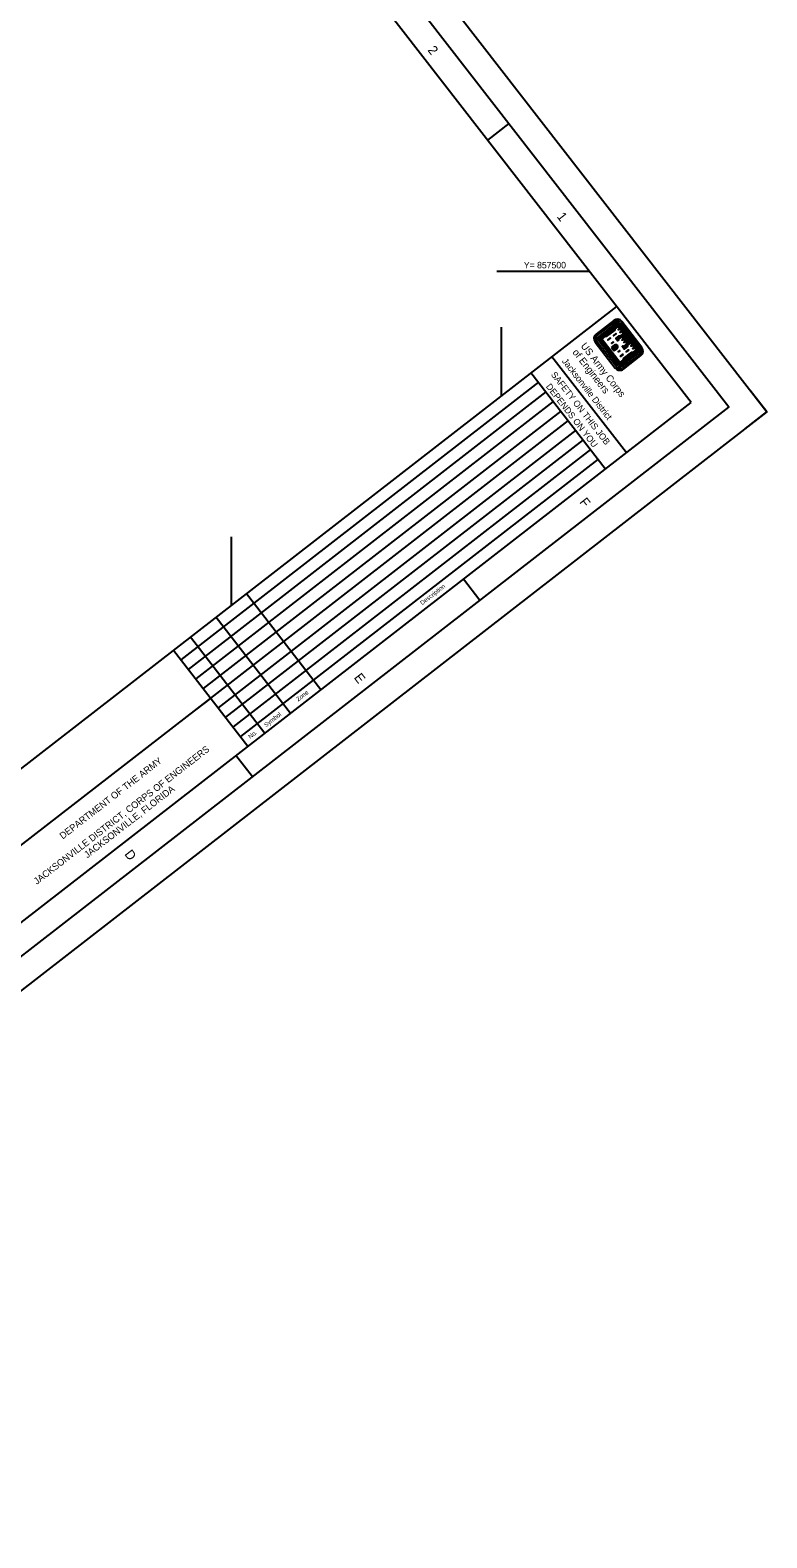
# Model space of a CAD drawing. Extents: x 577607 to 582991, y 855154 to 860715.
# Drawn here: x 581627 to 582991, y 855154 to 857946 of the extents above; entities that cross this region are included whole.
import ezdxf

# ---------------------------------------------------------------- set-up
doc = ezdxf.new("R2010")
doc.units = 0
for name, color, linetype in [('G-ANNO-NPLT', 7, 'Continuous'), ('G-ANNO-TEXT-LOGO', 7, 'Continuous'), ('G-ANNO-TEXT-TTLB', 7, 'Continuous'), ('G-ANNO-TTLB', 7, 'Continuous'), ('V-TOPO-COOR-STAT', 7, 'Continuous')]:
    doc.layers.add(name, color=color, linetype=linetype)

msp = doc.modelspace()

# ---------------------------------------------------------------- linework, layer by layer
at = {"layer": 'G-ANNO-NPLT'}
msp.add_lwpolyline([(580293.3, 860714.9), (582991.2, 857239.1), (580305.4, 855154.4), (577607.4, 858630.1)], close=True, dxfattribs=at)
msp.add_lwpolyline([(582951.7, 857208.5), (582991.2, 857239.1), (582960.5, 857278.6)], dxfattribs=at)
at = {"layer": 'G-ANNO-TEXT-LOGO'}
for p, q in [((582707.7, 857408.5), (582675.3, 857383.4)), ((582677.3, 857380.9), (582709.7, 857406)), ((582720.2, 857404.7), (582757.5, 857356.6)), ((582760, 857358.6), (582722.7, 857406.6)), ((582711.8, 857403.2), (582679.4, 857378.1)), ((582712.3, 857402.5), (582680, 857377.4)), ((582712.8, 857401.9), (582680.5, 857376.7)), ((582713.4, 857401.2), (582681, 857376)), ((582713.9, 857400.5), (582681.6, 857375.3)), ((582714.5, 857399.8), (582682.3, 857374.8)), ((582715, 857399.1), (582683.5, 857374.7)), ((582708.5, 857393.2), (582692, 857380.4)), ((582708.4, 857392), (582693.3, 857380.3)), ((582752, 857352.4), (582714.7, 857400.4)), ((582752.7, 857353), (582715.4, 857401)), ((582753.3, 857353.5), (582716.1, 857401.5)), ((582754.1, 857354), (582716.8, 857402)), ((582754.8, 857354.6), (582717.5, 857402.6)), ((582722.9, 857380.1), (582734.3, 857365.4)), ((582723.6, 857380.6), (582735, 857366)), ((582724.3, 857381.1), (582735.7, 857366.4)), ((582725, 857381.7), (582736.4, 857367)), ((582725.7, 857382.2), (582737.1, 857367.5)), ((582726.3, 857382.7), (582737.7, 857368)), ((582727, 857383.3), (582738.4, 857368.6)), ((582673.3, 857368.3), (582710.6, 857320.3)), ((582713.2, 857322.3), (582675.9, 857370.3)), ((582716, 857324.4), (582678.7, 857372.5)), ((582716.6, 857324.9), (582679.3, 857373)), ((582717.3, 857325.5), (582680, 857373.5)), ((582718, 857326), (582680.8, 857374.1)), ((582718.7, 857326.5), (582681.4, 857374.6)), ((582719.1, 857327.4), (582682.3, 857374.8)), ((582719.4, 857328.6), (582683.5, 857374.7)), ((582703.7, 857358.4), (582709, 857362.5)), ((582703.7, 857358.4), (582708.6, 857352.1)), ((582704.1, 857357.8), (582709.4, 857361.9)), ((582704.7, 857357.1), (582710, 857361.2)), ((582705.3, 857356.4), (582710.5, 857360.5)), ((582705.7, 857355.7), (582711, 857359.9)), ((582706.5, 857354.8), (582711.8, 857358.9)), ((582707, 857354.2), (582712.3, 857358.3)), ((582707.5, 857353.5), (582712.8, 857357.6)), ((582708.1, 857352.7), (582713.4, 857356.9)), ((582708.6, 857352.1), (582713.9, 857356.2)), ((582751.3, 857352.4), (582719.1, 857327.4)), ((582750.8, 857353), (582719.4, 857328.6)), ((582751.8, 857351.6), (582719.4, 857326.5)), ((582752.4, 857350.9), (582720, 857325.8)), ((582752.9, 857350.3), (582720.5, 857325.2)), ((582753.4, 857349.6), (582721, 857324.5)), ((582754, 857348.9), (582721.6, 857323.7)), ((582743.4, 857348.1), (582727, 857335.4)), ((582742.2, 857348.4), (582727.1, 857336.7)), ((582756.1, 857346.2), (582723.7, 857321.1)), ((582725.7, 857318.4), (582758.1, 857343.6))]:
    msp.add_line(p, q, dxfattribs=at)
for points in [[(582715.4, 857398.6), (582709.2, 857393.7), (582708.9, 857391.3), (582693.8, 857379.6), (582691.3, 857379.9), (582684.4, 857374.5), (582719.4, 857329.5), (582726.3, 857334.8), (582726.6, 857337.4), (582741.7, 857349.1), (582744.1, 857348.7), (582750.4, 857353.5), (582745.8, 857359.5), (582742.2, 857364), (582738.9, 857368.3), (582732.7, 857363.5), (582732.5, 857360.9), (582727, 857356.6), (582724.4, 857360), (582724.9, 857360.4), (582727.5, 857360.1), (582733.6, 857364.8), (582729, 857370.8), (582725.5, 857375.4), (582722.2, 857379.5), (582716, 857374.8), (582715.7, 857372.2), (582715.2, 857371.8), (582712.6, 857375.1), (582718.1, 857379.4), (582720.6, 857379), (582726.8, 857383.9), (582722.2, 857389.8), (582718.7, 857394.4), (582715.4, 857398.6)], [(582715.2, 857397.4), (582710, 857393.3), (582709.7, 857390.8), (582694, 857378.7), (582691.5, 857379), (582685.7, 857374.5), (582719.6, 857330.7), (582725.5, 857335.2), (582725.7, 857337.8), (582741.4, 857350), (582744, 857349.6), (582749.2, 857353.6), (582745.9, 857357.9), (582743.4, 857356), (582743.1, 857356.4), (582745.5, 857358.3), (582742.3, 857362.5), (582739.8, 857360.6), (582739.6, 857360.9), (582742.1, 857362.8), (582738.7, 857367.1), (582733.5, 857363), (582733.2, 857360.5), (582726.8, 857355.5), (582723.3, 857360.1), (582724.8, 857361.3), (582727.3, 857360.9), (582732.5, 857365), (582729.2, 857369.3), (582726.7, 857367.4), (582726.5, 857367.7), (582728.9, 857369.6), (582725.6, 857373.8), (582723.2, 857371.9), (582722.9, 857372.3), (582725.3, 857374.2), (582722.1, 857378.4), (582716.9, 857374.4), (582716.5, 857371.8), (582715, 857370.7), (582711.5, 857375.3), (582717.9, 857380.2), (582720.4, 857379.9), (582725.6, 857384), (582722.4, 857388.1), (582719.9, 857386.2), (582719.6, 857386.6), (582722.1, 857388.5), (582718.8, 857392.8), (582716.3, 857390.9), (582716.1, 857391.2), (582718.5, 857393.1), (582715.2, 857397.4)], [(582701.3, 857376.2), (582696.6, 857372.6), (582697, 857372.1), (582701.6, 857375.7), (582701.3, 857376.2)], [(582711.8, 857384.3), (582707.2, 857380.8), (582707.6, 857380.3), (582712.1, 857383.9), (582711.8, 857384.3)], [(582719.1, 857378.4), (582718.4, 857378.5), (582713.9, 857375), (582715, 857373.5), (582715.3, 857375.3), (582719.2, 857378.3)], [(582706.9, 857368.9), (582703.7, 857366.4), (582704, 857366), (582707.2, 857368.5), (582706.9, 857368.9)], [(582719.5, 857352.7), (582716.3, 857350.1), (582716, 857350.5), (582719.2, 857353), (582719.5, 857352.7)], [(582731.7, 857362.1), (582731.6, 857361.4), (582727.1, 857357.9), (582726, 857359.3), (582727.8, 857359.2), (582731.7, 857362.2)], [(582735.6, 857353.6), (582731, 857350.1), (582730.7, 857350.5), (582735.3, 857354), (582735.6, 857353.6)], [(582725.1, 857345.5), (582720.5, 857341.8), (582720.1, 857342.2), (582724.8, 857345.9), (582725.1, 857345.5)]]:
    msp.add_lwpolyline(points, dxfattribs=at)
for centre, major_axis, start_param, end_param in [((582714.3, 857400.1), (6.57, -8.46), 1.57078, 3.141576), ((582714.3, 857400.1), (4.59, -5.92), 1.57078, 3.141576), ((582714.3, 857400.1), (2.46, -3.17), 1.57078, 3.141576), ((582681.8, 857374.9), (-6.57, 8.46), 6.28317, 7.853966), ((582681.8, 857374.9), (-4.59, 5.92), 6.28317, 7.853966), ((582681.8, 857374.9), (-2.46, 3.17), 6.28317, 7.853966), ((582681.8, 857374.9), (-1.93, 2.49), 6.28317, 7.853966), ((582681.8, 857374.9), (-1.4, 1.8), 6.28317, 7.853966), ((582681.8, 857374.9), (-0.87, 1.12), 6.28317, 7.853966), ((582714.3, 857400.1), (1.93, -2.49), 1.57078, 3.141576), ((582714.3, 857400.1), (1.4, -1.8), 1.57078, 3.141576), ((582714.3, 857400.1), (0.87, -1.12), 1.57078, 3.141576), ((582714.3, 857400.1), (0.335, -0.431), 1.57078, 3.141576), ((582681.8, 857374.9), (-0.335, 0.431), 6.28317, 7.853966), ((582712, 857357.9), (-3.41, 4.39), 4.985832, 6.214359), ((582712, 857357.9), (-2.87, 3.7), 4.947465, 6.21436), ((582712, 857357.9), (-2.34, 3.02), 4.947465, 6.21436), ((582712, 857357.9), (-1.81, 2.33), 4.947465, 6.21436), ((582712, 857357.9), (-1.28, 1.64), 4.947465, 6.214359), ((582710.1, 857360.3), (1.28, -1.64), 0.068794, 1.335689), ((582710.1, 857360.3), (1.81, -2.33), 0.068794, 1.335689), ((582710.1, 857360.3), (2.34, -3.02), 0.068795, 1.335689), ((582710.1, 857360.3), (2.87, -3.7), 0.068795, 1.335689), ((582710.1, 857360.3), (3.41, -4.39), 0.068795, 1.29842), ((582751.5, 857352.1), (0.335, -0.431), 6.283169, 7.853965), ((582751.5, 857352.1), (0.87, -1.12), 6.283169, 7.853965), ((582751.5, 857352.1), (1.4, -1.8), 6.283169, 7.853965), ((582751.5, 857352.1), (1.93, -2.49), 6.283169, 7.853965), ((582751.5, 857352.1), (2.46, -3.17), 6.283169, 7.853965), ((582751.5, 857352.1), (4.59, -5.92), 6.28317, 7.853966), ((582751.5, 857352.1), (6.57, -8.46), 6.283169, 7.853965), ((582719.1, 857326.9), (6.57, -8.46), 4.712373, 6.28317), ((582719.1, 857326.9), (-4.59, 5.92), 1.570781, 3.141577), ((582719.1, 857326.9), (2.46, -3.17), 4.712373, 6.28317), ((582719.1, 857326.9), (1.93, -2.49), 4.712373, 6.28317), ((582719.1, 857326.9), (1.4, -1.8), 4.712373, 6.28317), ((582719.1, 857326.9), (0.87, -1.12), 4.712373, 6.28317), ((582719.1, 857326.9), (0.335, -0.431), 4.712373, 6.28317)]:
    msp.add_ellipse(centre, major_axis=major_axis, ratio=0.99964, start_param=start_param, end_param=end_param, dxfattribs=at)
at = {"layer": 'G-ANNO-TTLB'}
for p, q in [((582513.3, 857773.3), (582473.8, 857742.6)), ((582712.9, 857434.6), (580185.1, 855472.4)), ((582593.4, 857341.8), (582731.4, 857164.1)), ((582568.3, 857294.1), (581906.4, 856780.3)), ((582554.3, 857312.2), (582692.2, 857134.5)), ((582582.1, 857276.3), (581920.2, 856762.5)), ((582595.9, 857258.5), (581934, 856744.7)), ((582609.7, 857240.8), (581947.8, 856727)), ((582623.5, 857223), (581961.6, 856709.2)), ((582637.3, 857205.2), (581975.4, 856691.4)), ((582651.1, 857187.4), (581989.2, 856673.7)), ((582664.9, 857169.7), (582003, 856655.9)), ((582678.7, 857151.9), (582016.8, 856638.1)), ((582460.1, 856890.2), (582429.4, 856929.7)), ((582027.8, 856902.8), (582165.8, 856725)), ((581971.6, 856859.1), (582109.6, 856681.4)), ((581924.2, 856822.4), (582062.1, 856644.6)), ((581892.7, 856797.9), (582030.7, 856620.2)), ((581282.3, 856182.5), (581961.7, 856709)), ((581961.7, 856709), (581933.7, 856687.4)), ((582038.8, 856563.2), (582008.2, 856602.7))]:
    msp.add_line(p, q, dxfattribs=at)
for points in [[(577677.6, 858621.3), (580314.2, 855224.5), (582921, 857248), (580284.4, 860644.7)], [(582850.9, 857256.8), (580321.6, 860515.3), (577793.7, 858553.2), (580323.1, 855294.7)]]:
    msp.add_lwpolyline(points, close=True, dxfattribs=at)
at = {"layer": 'V-TOPO-COOR-STAT'}
for p, q in [((582491.2, 857500), (582662.1, 857500)), ((582500, 857269.3), (582500, 857395.9)), ((582000, 856881.2), (582000, 857007.8))]:
    msp.add_line(p, q, dxfattribs=at)

# ---------------------------------------------------------------- texts
at = {"layer": 'G-ANNO-TEXT-TTLB'}
for s, height, rotation, p in [('of Engineers', 13.086, 307.8192, (582630.6, 857349.2)), ('US Army Corps', 13.086, 307.8192, (582645.9, 857361.1)), ('Jacksonville District', 11.9, 307.8192, (582611.2, 857332.9)), ('DEPENDS ON YOU', 11.9, 307.8192, (582581.5, 857285.9)), ('SAFETY ON THIS JOB', 11.9, 307.8192, (582590.8, 857308)), ('Description', 8, 37.8192, (582353.2, 856881.1)), ('Zone', 8, 37.8192, (582123.7, 856702.6)), ('Symbol', 8, 37.8192, (582064.1, 856654.9)), ('No.', 8, 37.8192, (582035, 856633.5)), ('JACKSONVILLE DISTRICT, CORPS OF ENGINEERS', 12.5, 37.8192, (581640, 856363.3)), ('DEPARTMENT OF THE ARMY', 12.5, 37.8192, (581687.9, 856447.3)), ('JACKSONVILLE, FLORIDA', 12.5, 37.8192, (581733.3, 856412.3))]:
    msp.add_text(s, height=height, rotation=rotation, dxfattribs=at).set_placement(p)
at = {"layer": 'G-ANNO-TTLB'}
for s, p in [('2', (582362.4, 857908.8)), ('1', (582601.5, 857600.7)), ('F', (582643.3, 857071.9)), ('E', (582226, 856747)), ('D', (581801.2, 856420.1))]:
    msp.add_text(s, height=17.5, rotation=307.8192, dxfattribs=at).set_placement(p)
at = {"layer": 'V-TOPO-COOR-STAT'}
msp.add_text('Y= 857500', height=12, dxfattribs=at).set_placement((582541.3, 857505))

doc.saveas('drawing.dxf')
